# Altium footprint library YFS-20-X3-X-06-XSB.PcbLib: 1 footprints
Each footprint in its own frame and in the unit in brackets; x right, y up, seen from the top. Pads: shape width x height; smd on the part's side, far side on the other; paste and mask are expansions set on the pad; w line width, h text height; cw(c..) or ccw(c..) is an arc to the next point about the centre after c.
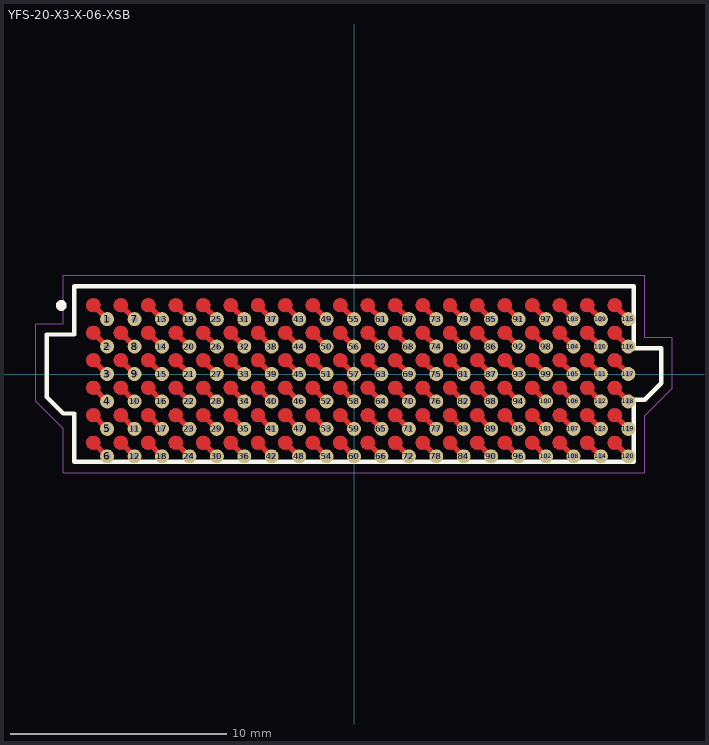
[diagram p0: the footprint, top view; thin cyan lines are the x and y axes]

## YFS-20-X3-X-06-XSB [mm] "1.27mm pitch, 120 pin, socket array; 6 rows, SMT"
height 3.4
pads (120):
  round 0.65 hole 0.3 unplated mask+0: 1(-11.43,2.54) 2(-11.43,1.27) 3(-11.43,0) 4(-11.43,-1.27) 5(-11.43,-2.54) 6(-11.43,-3.81) 7(-10.16,2.54) 8(-10.16,1.27) 9(-10.16,0) 10(-10.16,-1.27) 11(-10.16,-2.54) 12(-10.16,-3.81) 13(-8.89,2.54) 14(-8.89,1.27) 15(-8.89,0) 16(-8.89,-1.27) 17(-8.89,-2.54) 18(-8.89,-3.81) 19(-7.62,2.54) 20(-7.62,1.27) 21(-7.62,0) 22(-7.62,-1.27) 23(-7.62,-2.54) 24(-7.62,-3.81) 25(-6.35,2.54) 26(-6.35,1.27) 27(-6.35,0) 28(-6.35,-1.27) 29(-6.35,-2.54) 30(-6.35,-3.81) 31(-5.08,2.54) 32(-5.08,1.27) 33(-5.08,0) 34(-5.08,-1.27) 35(-5.08,-2.54) 36(-5.08,-3.81) 37(-3.81,2.54) 38(-3.81,1.27) 39(-3.81,0) 40(-3.81,-1.27) 41(-3.81,-2.54) 42(-3.81,-3.81) 43(-2.54,2.54) 44(-2.54,1.27) 45(-2.54,0) 46(-2.54,-1.27) 47(-2.54,-2.54) 48(-2.54,-3.81) 49(-1.27,2.54) 50(-1.27,1.27) 51(-1.27,0) 52(-1.27,-1.27) 53(-1.27,-2.54) 54(-1.27,-3.81) 55(0,2.54) 56(0,1.27) 57(0,0) 58(0,-1.27) 59(0,-2.54) 60(0,-3.81) 61(1.27,2.54) 62(1.27,1.27) 63(1.27,0) 64(1.27,-1.27) 65(1.27,-2.54) 66(1.27,-3.81) 67(2.54,2.54) 68(2.54,1.27) 69(2.54,0) 70(2.54,-1.27) 71(2.54,-2.54) 72(2.54,-3.81) 73(3.81,2.54) 74(3.81,1.27) 75(3.81,0) 76(3.81,-1.27) 77(3.81,-2.54) 78(3.81,-3.81) 79(5.08,2.54) 80(5.08,1.27) 81(5.08,0) 82(5.08,-1.27) 83(5.08,-2.54) 84(5.08,-3.81) 85(6.35,2.54) 86(6.35,1.27) 87(6.35,0) 88(6.35,-1.27) 89(6.35,-2.54) 90(6.35,-3.81) 91(7.62,2.54) 92(7.62,1.27) 93(7.62,0) 94(7.62,-1.27) 95(7.62,-2.54) 96(7.62,-3.81) 97(8.89,2.54) 98(8.89,1.27) 99(8.89,0) 100(8.89,-1.27) 101(8.89,-2.54) 102(8.89,-3.81) 103(10.16,2.54) 104(10.16,1.27) 105(10.16,0) 106(10.16,-1.27) 107(10.16,-2.54) 108(10.16,-3.81) 109(11.43,2.54) 110(11.43,1.27) 111(11.43,0) 112(11.43,-1.27) 113(11.43,-2.54) 114(11.43,-3.81) 115(12.7,2.54) 116(12.7,1.27) 117(12.7,0) 118(12.7,-1.27) 119(12.7,-2.54) 120(12.7,-3.81)
Top Layer:
  drawing of 240 lines, arcs and shapes, not listed
Top Overlay:
  circle w0.25: c-13.554,3.175 r0.125
  lines w0.2: -14.224,-1.067 -14.224,1.829 -12.954,1.829 -12.954,4.064 12.954,4.064 12.954,1.194 14.224,1.194 14.224,-0.432 13.462,-1.194 12.954,-1.194 12.954,-4.064 -12.954,-4.064 -12.954,-1.829 -13.462,-1.829 -14.224,-1.067
Top Paste:
  drawing of 120 lines, arcs and shapes, not listed
Top Solder:
  drawing of 120 lines, arcs and shapes, not listed
Mechanical 12:
  lines w0.001: -14.224,-1.067 -14.224,1.829 -12.954,1.829 -12.954,4.064 12.954,4.064 12.954,1.194 14.224,1.194 14.224,-0.432 13.462,-1.194 12.954,-1.194 12.954,-4.064 -12.954,-4.064 -12.954,-1.829 -13.462,-1.829 -14.224,-1.067
Mechanical 13:
  drawing of 148 lines, arcs and shapes, not listed
  text ".Designator" at 0,0 h1.52
Mechanical 15:
  lines w0.05: -0.5,0 0.5,0 ; 0,-0.5 0,0.5 ; -14.732,-1.257 -14.732,2.337 -13.462,2.337 -13.462,4.572 13.462,4.572 13.462,1.702 14.732,1.702 14.732,-0.66 13.462,-1.93 13.462,-4.572 -13.462,-4.572 -13.462,-2.527 -14.732,-1.257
